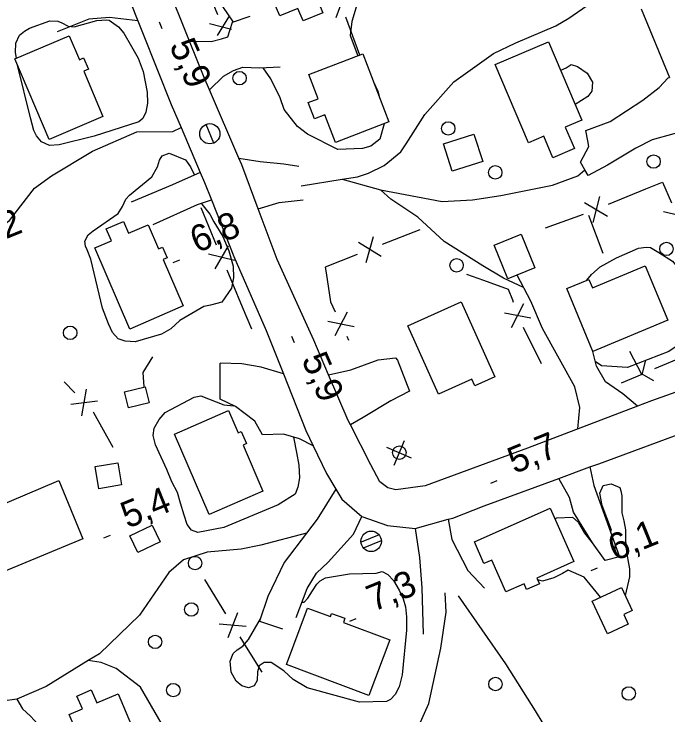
# Model space of a CAD drawing. Extents: x 362852 to 366875, y 5563573 to 5566479.
# Drawn here: x 364061.2 to 364158.5, y 5564712.5 to 5564816.7 of the extents above; entities that cross this region are included whole.
import ezdxf

# ---------------------------------------------------------------- set-up
doc = ezdxf.new("R2010")
doc.units = 0
for name, color, linetype in [('Niveau 19', 7, 'Continuous'), ('Niveau 2', 7, 'Continuous'), ('Niveau 21', 7, 'Continuous'), ('Niveau 22', 7, 'Continuous'), ('Niveau 3', 7, 'Continuous'), ('Niveau 31', 7, 'Continuous'), ('Niveau 36', 7, 'Continuous'), ('Niveau 37', 7, 'Continuous')]:
    doc.layers.add(name, color=color, linetype=linetype)

msp = doc.modelspace()

# ---------------------------------------------------------------- linework, layer by layer
at = {"layer": 'Niveau 19'}
for points in [[(364079.63, 5564815.66), (364075.41, 5564816.18), (364072.32, 5564815.9), (364067.62, 5564814.03)], [(364087.31, 5564812.64), (364090.54, 5564812.59), (364092.07, 5564812.97), (364093, 5564813.28), (364093.71, 5564815.44), (364096.32, 5564816.38)], [(364090.28, 5564805.39), (364092.36, 5564807.42), (364093.87, 5564808.29), (364095.23, 5564808.78), (364097.73, 5564808.68), (364100.79, 5564808.81)], [(364162.31, 5564798.95), (364159.34, 5564798.85), (364156.12, 5564797.97), (364153.67, 5564796.72), (364149.47, 5564794.19), (364146.59, 5564792.7), (364146.12, 5564793.54), (364145.48, 5564794.67), (364146.69, 5564796.98), (364146.53, 5564797.84), (364146.23, 5564799.34), (364149.87, 5564800.71), (364154.72, 5564803.87), (364157.16, 5564805.74), (364158.51, 5564807.17), (364158.71, 5564807.25)], [(364094.64, 5564795.27), (364097.82, 5564794.77), (364101.35, 5564794.42), (364103.56, 5564794.08)], [(364088.91, 5564793.12), (364084.75, 5564791.28), (364078.61, 5564788.71)], [(364081.9, 5564785.38), (364088.48, 5564788.39), (364090.57, 5564789.06)], [(364097.52, 5564787.74), (364100.63, 5564788.64), (364104.22, 5564789.05)], [(364145.06, 5564755.02), (364145.38, 5564758.22), (364144.61, 5564761.26), (364139.81, 5564769.94), (364138.06, 5564774.02), (364136.03, 5564777.86)], [(364153.94, 5564758.42), (364151.76, 5564760.21), (364149.16, 5564762.01), (364147.82, 5564764.32), (364147.31, 5564766.52)], [(364107.99, 5564763.07), (364111.29, 5564763.8), (364115.38, 5564765.29), (364117.93, 5564765.59), (364118.26, 5564765.23), (364120, 5564760.65), (364117.23, 5564759.2), (364113.12, 5564756.71), (364111.23, 5564755.62)], [(364101.29, 5564763.19), (364097.97, 5564764.2), (364095.11, 5564764.71), (364091.84, 5564764.81)], [(364105.72, 5564752.5), (364103.68, 5564753.53), (364101.29, 5564754.24), (364098.16, 5564754.14), (364097.03, 5564756.16), (364094.14, 5564758.34), (364091.85, 5564759.46), (364091.84, 5564764.81)], [(364146.85, 5564749.36), (364147.45, 5564746.62), (364151.27, 5564736), (364149.14, 5564735.44), (364147.25, 5564738.09), (364144.43, 5564742.65), (364143.8, 5564744.81), (364142.22, 5564747.67)], [(364109.07, 5564746.08), (364106.27, 5564741.59), (364104.69, 5564739.52), (364101.38, 5564735.16), (364098.96, 5564730.13), (364097.73, 5564726.46), (364101.12, 5564725.3)], [(364103.16, 5564727.01), (364104.81, 5564731.29), (364106.19, 5564733.59), (364107.92, 5564735.23), (364111.68, 5564739.38), (364112.92, 5564742.01)], [(364125.78, 5564741.58), (364126.33, 5564738.6), (364128.68, 5564733.96), (364131.16, 5564731.37)], [(364120.86, 5564740.22), (364121.53, 5564735.89), (364121.88, 5564731.42), (364122.04, 5564724.52)]]:
    msp.add_lwpolyline(points, dxfattribs=at)
at = {"layer": 'Niveau 2'}
for points in [[(364093.83, 5564815.48), (364092.26, 5564817.8), (364087.42, 5564826.66), (364083.81, 5564834.32)], [(364148.4, 5564831.18), (364141.48, 5564828.99), (364138.3, 5564828.56), (364136.33, 5564827.88), (364127.95, 5564823.7), (364125.65, 5564822.63), (364122.66, 5564822.03), (364116.54, 5564821.14), (364115.43, 5564820.81), (364114.45, 5564820.16), (364112.09, 5564817.7), (364111.46, 5564815.58), (364111.2, 5564813.48), (364112.32, 5564810.46)], [(364061.56, 5564810.1), (364061.44, 5564810.97), (364061.49, 5564812.36), (364062.02, 5564813.51), (364062.77, 5564814.13), (364063.52, 5564814.57), (364066.55, 5564815.68), (364067.71, 5564815.59), (364068.31, 5564815.34), (364069.25, 5564814.86), (364070.15, 5564814.79), (364073.51, 5564815.73), (364075.03, 5564815.79), (364075.37, 5564815.74)], [(364075.37, 5564815.74), (364076.76, 5564814.76), (364077.52, 5564813.82), (364078.68, 5564811.87), (364079.66, 5564810.09), (364080.39, 5564808.14), (364081.03, 5564805.04), (364081.06, 5564803.44), (364080.8, 5564802.09), (364080.37, 5564801.16), (364079.76, 5564800.66), (364073.11, 5564798.5), (364067.9, 5564797.24), (364066.5, 5564797.16), (364065.3, 5564797.67), (364064.56, 5564798.55), (364064.16, 5564799.38), (364063.66, 5564801.23), (364061.72, 5564809.08)], [(364116.27, 5564800.37), (364115.59, 5564798.09), (364114.27, 5564797.05), (364113.05, 5564796.68), (364109.37, 5564796.54), (364104.85, 5564798.8), (364103.39, 5564799.94), (364101.36, 5564802.47), (364100.77, 5564804.22), (364099.39, 5564807.02), (364098.27, 5564808.7)], [(364142.51, 5564808.34), (364143.32, 5564808.7), (364144.06, 5564809.18)], [(364144.06, 5564809.18), (364144.99, 5564808.88), (364146.46, 5564807.86), (364147.24, 5564806.56), (364147.16, 5564805.22), (364146.55, 5564804.42), (364144.68, 5564803.23)], [(364114.67, 5564806.58), (364115.31, 5564805.2), (364115.56, 5564804.26)], [(364090.32, 5564786.93), (364090.91, 5564785.8), (364092.24, 5564783.61), (364093.16, 5564781.5), (364093.78, 5564779.2), (364093.86, 5564777.49), (364093.56, 5564775.93), (364092.1, 5564773.84), (364090.42, 5564773.4), (364089.45, 5564773.19), (364085.88, 5564771.11), (364084.52, 5564769.87), (364083.14, 5564769.12), (364079.2, 5564767.94), (364077.72, 5564768.08), (364076.71, 5564768.41), (364075.83, 5564769.36), (364075.25, 5564770.62), (364074.35, 5564772.98), (364072.64, 5564780.25), (364072.07, 5564781.64), (364071.85, 5564782.17), (364071.73, 5564782.93), (364072.22, 5564783.88), (364072.98, 5564784.44), (364076.67, 5564787.01), (364077.35, 5564788.09), (364077.84, 5564789.17), (364078.4, 5564789.77), (364081.71, 5564792.5), (364082.55, 5564793.96), (364082.83, 5564794.95), (364083.24, 5564795.61), (364084.28, 5564795.98), (364086.73, 5564794.99), (364087.46, 5564793.98), (364087.95, 5564792.93), (364088, 5564792.72)], [(364089.11, 5564788.59), (364089.15, 5564788.44), (364090.32, 5564786.93)], [(364146.41, 5564777.11), (364147.11, 5564777.94), (364148.39, 5564779.09), (364150.82, 5564780.46), (364154.1, 5564781.86), (364155.22, 5564782.01), (364155.86, 5564781.96), (364157.1, 5564781.22), (364159.12, 5564779.93)], [(364159.12, 5564779.93), (364160.04, 5564778.88), (364160.93, 5564777.31), (364161.48, 5564775.8), (364161.76, 5564774.35), (364161.99, 5564772.71), (364162.01, 5564770.97), (364161.61, 5564769.19), (364161.18, 5564768.27), (364158.59, 5564766.53), (364152.47, 5564764.14), (364148.57, 5564764.41), (364147.66, 5564765.02)], [(364102.75, 5564753.81), (364102.8, 5564753.52), (364103.24, 5564751.52), (364103.58, 5564749.61), (364103.65, 5564747.77), (364103.41, 5564746.36), (364103.02, 5564745.33), (364100.5, 5564743.74), (364092.42, 5564740.37), (364088.56, 5564739.6), (364087.61, 5564739.96), (364086.95, 5564740.81), (364086.51, 5564742.18), (364085.98, 5564743.96), (364085.51, 5564745.57), (364084.68, 5564747.16), (364083.94, 5564748.97), (364082.26, 5564752.64), (364081.88, 5564754.04), (364082.06, 5564755.11), (364082.78, 5564756.4), (364083.66, 5564757.44), (364088.02, 5564759.72), (364088.99, 5564759.94), (364092.4, 5564758.59), (364093.89, 5564758.46)], [(364149.93, 5564739.71), (364150.05, 5564739.95), (364148.68, 5564743.62), (364148.31, 5564745.46), (364148.84, 5564746.61), (364150.04, 5564746.85), (364151.32, 5564746.32), (364151.46, 5564745.82), (364151.58, 5564745.06), (364151.6, 5564742.57), (364151.91, 5564741.34)], [(364141.66, 5564741.66), (364141.96, 5564741.8), (364144.29, 5564741.89), (364145.09, 5564741.15), (364146.07, 5564739.5), (364147.2, 5564738.1), (364147.27, 5564738.06)], [(364151.91, 5564741.34), (364152.15, 5564740), (364152.16, 5564738.45), (364152.28, 5564736.76), (364152.52, 5564735.55), (364152.76, 5564734.22), (364152.74, 5564733.03), (364152.09, 5564730.28)], [(364115.97, 5564733.84), (364116.79, 5564733.36), (364117.65, 5564732.47), (364118.47, 5564731.07), (364119.06, 5564729.75), (364119.41, 5564728.59), (364119.58, 5564727.11), (364119.58, 5564725.12), (364118.94, 5564718.45), (364118.47, 5564716.7), (364117.88, 5564715.53), (364117.18, 5564714.81), (364116.62, 5564714.51), (364112.61, 5564714.43), (364104.8, 5564716.52), (364102.73, 5564717.78), (364101.33, 5564719.08), (364099.46, 5564720.3), (364098.41, 5564720.3), (364097.67, 5564719.82), (364097.42, 5564718.91), (364097.37, 5564717.64), (364096.9, 5564716.83), (364096.08, 5564716.55), (364095.09, 5564716.83), (364094.24, 5564717.54), (364093.52, 5564718.86), (364093.36, 5564720.48), (364093.81, 5564721.66), (364094.4, 5564722.21), (364095.24, 5564722.74), (364096.09, 5564723.71), (364097.85, 5564726.81)], [(364104.03, 5564729.25), (364104.34, 5564729.26), (364104.9, 5564729.87), (364105.58, 5564730.95), (364106.22, 5564731.96), (364106.72, 5564732.42), (364107.53, 5564732.87), (364111.09, 5564733.46), (364115.07, 5564733.6), (364115.97, 5564733.84)], [(364148.43, 5564730.02), (364148.22, 5564730.24), (364145.98, 5564733), (364143.63, 5564734.03), (364142.77, 5564733.55), (364141.48, 5564732.9), (364139.81, 5564732.4), (364139.1, 5564732.59)]]:
    msp.add_lwpolyline(points, dxfattribs=at)
at = {"layer": 'Niveau 21'}
for points in [[(364076.48, 5564823.59), (364076.68, 5564823.11), (364079.63, 5564815.66), (364080.31, 5564813.95), (364084.6, 5564803.25), (364086.07, 5564799.8), (364088.91, 5564793.12), (364089.55, 5564791.63), (364090.57, 5564789.06), (364093.92, 5564780.66), (364098.73, 5564769.62), (364101.29, 5564763.19), (364104.63, 5564754.8), (364105.72, 5564752.5), (364107.68, 5564748.39), (364109.07, 5564746.08), (364109.96, 5564744.6), (364112.92, 5564742.01), (364116.76, 5564740.66), (364120.86, 5564740.22)], [(364168.58, 5564763.67), (364156.02, 5564759.21), (364153.94, 5564758.42), (364137.55, 5564752.15), (364122.35, 5564746.55), (364117.99, 5564745.95), (364116.8, 5564746.27), (364115.63, 5564747.16), (364114.28, 5564749.66), (364111.23, 5564755.62), (364110.91, 5564756.25), (364107.99, 5564763.07), (364105.79, 5564768.21), (364100.36, 5564780.18), (364097.52, 5564787.74), (364095.07, 5564794.27), (364094.64, 5564795.27), (364090.28, 5564805.39), (364089.48, 5564807.24), (364087.31, 5564812.64), (364083.76, 5564821.46)], [(364154.47, 5564817.47), (364158.71, 5564807.25)], [(364120.86, 5564740.22), (364125.78, 5564741.58), (364126.48, 5564741.77), (364131.11, 5564743.61), (364142.22, 5564747.67), (364146.85, 5564749.36), (364148.19, 5564749.85), (364160.77, 5564754.5)]]:
    msp.add_lwpolyline(points, dxfattribs=at)
at = {"layer": 'Niveau 22'}
for points in [[(364103.93, 5564791.12), (364110.02, 5564792.11), (364112.29, 5564792.48), (364113.93, 5564793.03), (364116.26, 5564794.17), (364118.75, 5564796.18), (364119.51, 5564797.37), (364122.32, 5564801.76), (364126.62, 5564806.58), (364132.5, 5564810.79), (364135.83, 5564812.4), (364141.79, 5564814.9), (364143.74, 5564816.08), (364146.44, 5564817.93), (364147.3, 5564819.03), (364148.45, 5564820.87), (364148.94, 5564822.5), (364149.42, 5564827.05), (364149.52, 5564828.65)], [(364042.09, 5564784.74), (364044.88, 5564784.76), (364050.46, 5564783.56), (364054.36, 5564783.6), (364056.67, 5564784.05), (364058.74, 5564784.77), (364060.52, 5564786), (364064.24, 5564790.81), (364066.77, 5564792.65), (364072.87, 5564796.27), (364079.48, 5564799.16), (364084.84, 5564799.23), (364086.07, 5564799.8)], [(364110.02, 5564792.11), (364115.69, 5564790.57), (364124.9, 5564788.8), (364129.37, 5564789.08), (364133.6, 5564789.69), (364141.31, 5564791.23), (364145.07, 5564792.64), (364146.12, 5564793.54)], [(364137, 5564776.03), (364134.02, 5564777.4), (364130.93, 5564779.25), (364125.17, 5564782.87), (364121.24, 5564786.49), (364117.23, 5564789.15), (364115.69, 5564790.57)], [(364104.69, 5564739.52), (364097.9, 5564737.72), (364094.99, 5564737.15), (364089.92, 5564736.69), (364086.42, 5564735.57), (364084.21, 5564733.67), (364079.89, 5564727.35), (364073.9, 5564721.6), (364072.23, 5564720.58), (364066, 5564716.75), (364061.62, 5564714.83), (364057.33, 5564714.25), (364054.55, 5564714.42), (364051.5, 5564714.73), (364048.96, 5564715.31), (364047.26, 5564716.11)], [(364100.62, 5564654.91), (364102.02, 5564658.63), (364104.22, 5564667.67), (364105.49, 5564677.39), (364107.42, 5564684.1), (364114.55, 5564696.73), (364117.6, 5564702.73), (364118.88, 5564705.23), (364122.91, 5564714.23), (364124.7, 5564722.43), (364125.48, 5564727.79), (364125.34, 5564730.67)], [(364127.24, 5564730.19), (364134.29, 5564720.13), (364138.73, 5564713.11), (364147.86, 5564698.06), (364155.2, 5564688.49), (364162.63, 5564678.95)], [(364117.6, 5564702.73), (364112.99, 5564700.33), (364108.42, 5564699.64), (364104.18, 5564699.71), (364096.15, 5564700.47), (364092.31, 5564701.19), (364089.46, 5564703.27), (364086.48, 5564706.59), (364083.83, 5564710.05), (364080.01, 5564716.64), (364076.4, 5564719.39), (364074.17, 5564720.28), (364072.23, 5564720.58)], [(364061.62, 5564714.83), (364062.45, 5564713.42), (364063.63, 5564712.35), (364064.75, 5564711.13), (364066.28, 5564706.91), (364066.65, 5564704.94), (364066.45, 5564702.48), (364065.49, 5564700.41), (364061.94, 5564697.4), (364057.59, 5564695.01), (364050.57, 5564691.65), (364046.93, 5564689.91), (364043.72, 5564688.46)]]:
    msp.add_lwpolyline(points, dxfattribs=at)
at = {"layer": 'Niveau 3'}
for p, q in [((364082.8, 5564815.49), (364083.21, 5564814.54)), ((364084.89, 5564779.75), (364085.85, 5564780.14)), ((364102.46, 5564768.82), (364102.88, 5564767.87)), ((364132.12, 5564746.94), (364133.08, 5564747.33)), ((364074.58, 5564738.82), (364075.54, 5564739.21)), ((364147.05, 5564733.97), (364148.01, 5564734.36)), ((364111.13, 5564726.46), (364112.09, 5564726.85))]:
    msp.add_line(p, q, dxfattribs=at)
at = {"layer": 'Niveau 31'}
for points in [[(364103.44, 5564817.5), (364100.73, 5564816.39), (364099.61, 5564819.1), (364098.61, 5564818.69), (364097.52, 5564821.34), (364098.56, 5564821.77), (364095.94, 5564828.12), (364104.07, 5564831.47), (364108.88, 5564819.79), (364106.33, 5564818.74), (364107.11, 5564816.85), (364104.2, 5564815.65), (364103.44, 5564817.5)], [(364066.45, 5564798.05), (364061.33, 5564810), (364069.41, 5564813.45), (364070.93, 5564809.89), (364071.56, 5564810.16), (364072.28, 5564808.47), (364071.57, 5564808.16), (364074.43, 5564801.46), (364066.45, 5564798.05)], [(364137.7, 5564797.53), (364132.76, 5564809.15), (364140.72, 5564812.54), (364145.67, 5564800.91), (364143.2, 5564799.87), (364144.55, 5564796.69), (364141.34, 5564795.32), (364139.99, 5564798.5), (364137.7, 5564797.53)], [(364113.08, 5564810.75), (364116.94, 5564800.63), (364109, 5564797.6), (364107.43, 5564801.7), (364105.88, 5564801.11), (364104.97, 5564803.51), (364106.43, 5564804.07), (364105.05, 5564807.69), (364113.08, 5564810.75)], [(364125.06, 5564797.36), (364129.6, 5564798.84), (364130.93, 5564794.78), (364126.39, 5564793.3), (364125.06, 5564797.36)], [(364078.42, 5564769.84), (364073.2, 5564781.91), (364075.68, 5564782.98), (364074.92, 5564784.73), (364077.49, 5564785.84), (364078.25, 5564784.1), (364081.16, 5564785.36), (364082.71, 5564781.77), (364083.31, 5564782.03), (364084, 5564780.44), (364083.39, 5564780.17), (364086.37, 5564773.29), (364078.42, 5564769.84)], [(364134.63, 5564777.3), (364132.6, 5564782.3), (364136.65, 5564783.94), (364138.68, 5564778.95), (364134.63, 5564777.3)], [(364147.22, 5564775.99), (364155.08, 5564779.27), (364158.46, 5564771.17), (364147.31, 5564766.52), (364143.41, 5564775.86), (364146.7, 5564777.23), (364147.22, 5564775.99)], [(364127.72, 5564773.9), (364132.72, 5564762.74), (364129.74, 5564761.4), (364129.3, 5564762.39), (364124.35, 5564760.17), (364119.79, 5564770.34), (364127.72, 5564773.9)], [(364077.64, 5564760.53), (364080.69, 5564761.29), (364081.28, 5564758.91), (364078.24, 5564758.15), (364077.64, 5564760.53)], [(364090.22, 5564742.31), (364085.05, 5564754.26), (364093.1, 5564757.75), (364094.54, 5564754.43), (364095, 5564754.63), (364095.78, 5564752.83), (364095.26, 5564752.61), (364098.22, 5564745.77), (364090.22, 5564742.31)], [(364073.28, 5564749.43), (364076.64, 5564750), (364077.19, 5564746.69), (364073.83, 5564746.12), (364073.28, 5564749.43)], [(364058.17, 5564743.26), (364067.85, 5564747.34), (364071.44, 5564738.7), (364059.73, 5564733.83), (364058.36, 5564737.13), (364058.59, 5564737.23), (364056.39, 5564742.52), (364058.17, 5564743.26)], [(364129.67, 5564738.22), (364140.97, 5564743.22), (364144.48, 5564735.29), (364138.98, 5564732.86), (364139.36, 5564732), (364137.44, 5564731.15), (364137.06, 5564732.01), (364134.35, 5564730.81), (364132.27, 5564735.52), (364131.09, 5564735), (364129.67, 5564738.22)], [(364082.95, 5564738.22), (364079.64, 5564736.63), (364078.45, 5564739.11), (364081.76, 5564740.71), (364082.95, 5564738.22)], [(364147.18, 5564729.44), (364151.54, 5564731.46), (364153.14, 5564728.01), (364151.88, 5564727.43), (364152.55, 5564725.98), (364149.45, 5564724.54), (364147.18, 5564729.44)], [(364113.99, 5564715.4), (364101.72, 5564719.99), (364104.87, 5564728.4), (364108.26, 5564727.13), (364108.44, 5564727.61), (364110.43, 5564726.87), (364110.2, 5564726.27), (364117.1, 5564723.69), (364113.99, 5564715.4)], [(364076.67, 5564715.64), (364080.68, 5564706.25), (364073.45, 5564703.16), (364069.43, 5564712.56), (364071.39, 5564713.4), (364070.57, 5564715.31), (364072.7, 5564716.22), (364073.52, 5564714.3), (364076.67, 5564715.64)]]:
    msp.add_lwpolyline(points, dxfattribs=at)
at = {"layer": 'Niveau 36'}
for p, q in [((364090.9, 5564797.48), (364089.78, 5564800.26)), ((364117.73, 5564749.63), (364119.28, 5564753.3)), ((364120.34, 5564750.69), (364116.67, 5564752.24)), ((364115.5, 5564739.26), (364112.82, 5564738.17)), ((364113.16, 5564737.32), (364115.85, 5564738.41))]:
    msp.add_line(p, q, dxfattribs=at)
for centre, radius in [((364094.75, 5564807.14), 1), ((364090.33, 5564798.88), 1.5), ((364125.79, 5564799.67), 1), ((364156.33, 5564794.75), 1), ((364132.78, 5564793.14), 1), ((364158.24, 5564781.77), 1), ((364127.03, 5564779.33), 1), ((364069.55, 5564769.3), 1), ((364118.52, 5564751.49), 1), ((364114.32, 5564738.31), 1.52), ((364088.13, 5564735.08), 1), ((364087.58, 5564728.18), 1), ((364082.19, 5564723.37), 1), ((364132.81, 5564717.1), 1), ((364084.89, 5564716.2), 1), ((364152.63, 5564715.7), 1)]:
    msp.add_circle(centre, radius, dxfattribs=at)
at = {"layer": 'Niveau 37'}
for p, q in [((364089.22, 5564822.15), (364091.45, 5564816.58)), ((364109.1, 5564816.17), (364110.47, 5564819.93)), ((364093.23, 5564816.43), (364091.44, 5564813.5)), ((364112.62, 5564810.58), (364110.56, 5564816.22)), ((364093.57, 5564814.35), (364090.26, 5564815.24)), ((364149.63, 5564788.41), (364155.18, 5564790.68)), ((364148.28, 5564789.58), (364147.27, 5564785.71)), ((364088.98, 5564787.9), (364091.29, 5564782.36)), ((364146.06, 5564788.67), (364149.49, 5564786.62)), ((364140.27, 5564784.88), (364145.91, 5564786.92)), ((364148.83, 5564781.11), (364146.72, 5564786.73)), ((364161.7, 5564786.33), (364157.81, 5564787.27)), ((364121.56, 5564784.62), (364115.98, 5564782.41)), ((364113.6, 5564779.75), (364114.65, 5564783.61)), ((364115.83, 5564780.63), (364112.42, 5564782.73)), ((364093.07, 5564782.24), (364091.05, 5564778.8)), ((364094, 5564780.03), (364090.12, 5564781.01)), ((364131.07, 5564777.06), (364128.56, 5564777.97)), ((364135.21, 5564770.11), (364137.03, 5564773.67)), ((364095.16, 5564773.14), (364096.52, 5564769.89)), ((364110.77, 5564772.37), (364108.91, 5564768.83)), ((364134.16, 5564772.26), (364138.09, 5564771.52)), ((364111.8, 5564770.2), (364107.88, 5564771)), ((364139.64, 5564764.71), (364137, 5564770.1)), ((364110.7, 5564768.79), (364110.97, 5564768.22)), ((364154.58, 5564763.12), (364152.81, 5564766.5)), ((364161.99, 5564766.29), (364156.48, 5564763.93)), ((364154.62, 5564763.04), (364155.12, 5564765.09)), ((364154.58, 5564763.12), (364151.51, 5564761.81)), ((364156.37, 5564762.15), (364154.54, 5564763.2)), ((364070.24, 5564760.38), (364068.66, 5564762.03)), ((364071.3, 5564756.96), (364071.96, 5564760.9)), ((364069.64, 5564758.69), (364073.62, 5564759.17)), ((364089.53, 5564732.63), (364092.68, 5564727.52)), ((364094.46, 5564727.68), (364092.99, 5564723.96)), ((364095.72, 5564725.64), (364091.73, 5564726)), ((364097.94, 5564719.02), (364098.05, 5564718.85))]:
    msp.add_line(p, q, dxfattribs=at)
for points in [[(364155.18, 5564790.68), (364157.65, 5564791.69), (364158.97, 5564788.63)], [(364112.26, 5564780.94), (364107.49, 5564779.05), (364107.62, 5564778.19)], [(364092.84, 5564778.67), (364093.69, 5564776.63), (364095.16, 5564773.14)], [(364107.62, 5564778.19), (364108.28, 5564773.9), (364108.99, 5564772.4)], [(364135.49, 5564773.78), (364135.39, 5564774.17), (364134.76, 5564775.72), (364131.07, 5564777.06)], [(364080.56, 5564761.26), (364080.4, 5564763.42), (364081.85, 5564765.75)], [(364075.95, 5564752.26), (364073.06, 5564757.43), (364073.01, 5564757.49)], [(364094.78, 5564724.12), (364095.59, 5564722.81), (364097.94, 5564719.02)]]:
    msp.add_lwpolyline(points, dxfattribs=at)

# ---------------------------------------------------------------- texts
at = {"layer": 'Niveau 3'}
for s, rotation, p in [('5,9  ', 293.5017, (364084.25, 5564812.01)), ('5,2  ', 22.09, (364055.94, 5564781.55)), ('6,8  ', 22.09, (364088.4, 5564781.11)), ('5,9  ', 293.6752, (364103.91, 5564765.35)), ('5,7  ', 22.09, (364135.63, 5564748.3)), ('5,4  ', 22.09, (364078.09, 5564740.18)), ('6,1  ', 22.09, (364150.56, 5564735.33)), ('7,3  ', 22.09, (364114.64, 5564727.82))]:
    msp.add_text(s, height=3.93, rotation=rotation, dxfattribs=at).set_placement(p)

doc.saveas('drawing.dxf')
